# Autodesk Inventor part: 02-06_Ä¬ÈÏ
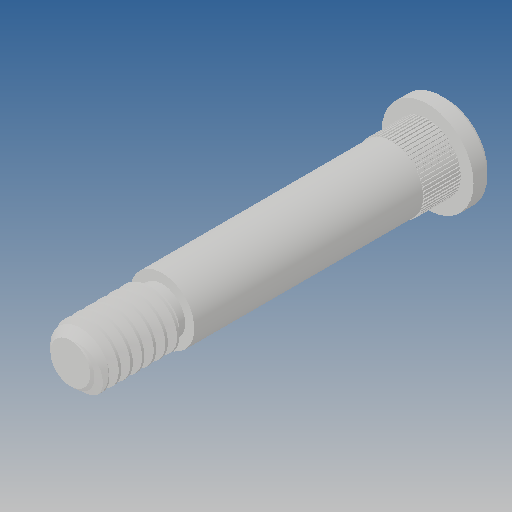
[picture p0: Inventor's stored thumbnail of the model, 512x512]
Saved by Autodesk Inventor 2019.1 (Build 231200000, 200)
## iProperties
Created: 2010-06
Part Number: 02-06_Ä¬ÈÏ
Material: Ogólny
Document SubType Name: Modeling
Designer: CADENGINEERING4
Density: 1 g/cm^3
Appearance: Domyślna
Author: CADENGINEERING4
Revision Number: ÈÎºÎ
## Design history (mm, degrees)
feature "NONE"
node "Bryła1"
